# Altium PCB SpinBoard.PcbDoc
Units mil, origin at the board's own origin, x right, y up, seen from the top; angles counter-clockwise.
Board outline 4528 x 1083 mil, 2 copper layers (Top Layer, Bottom Layer), stack 26.422 mil thick; 101 components, 94 nets, 297 pads, 156 vias.
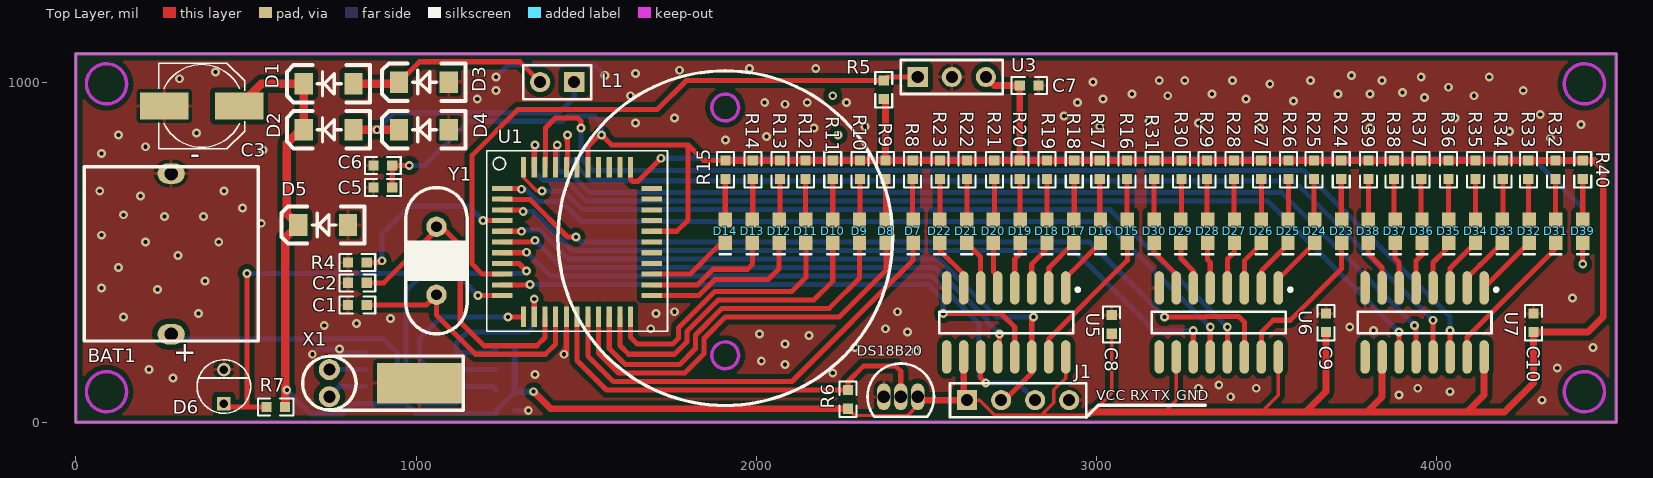
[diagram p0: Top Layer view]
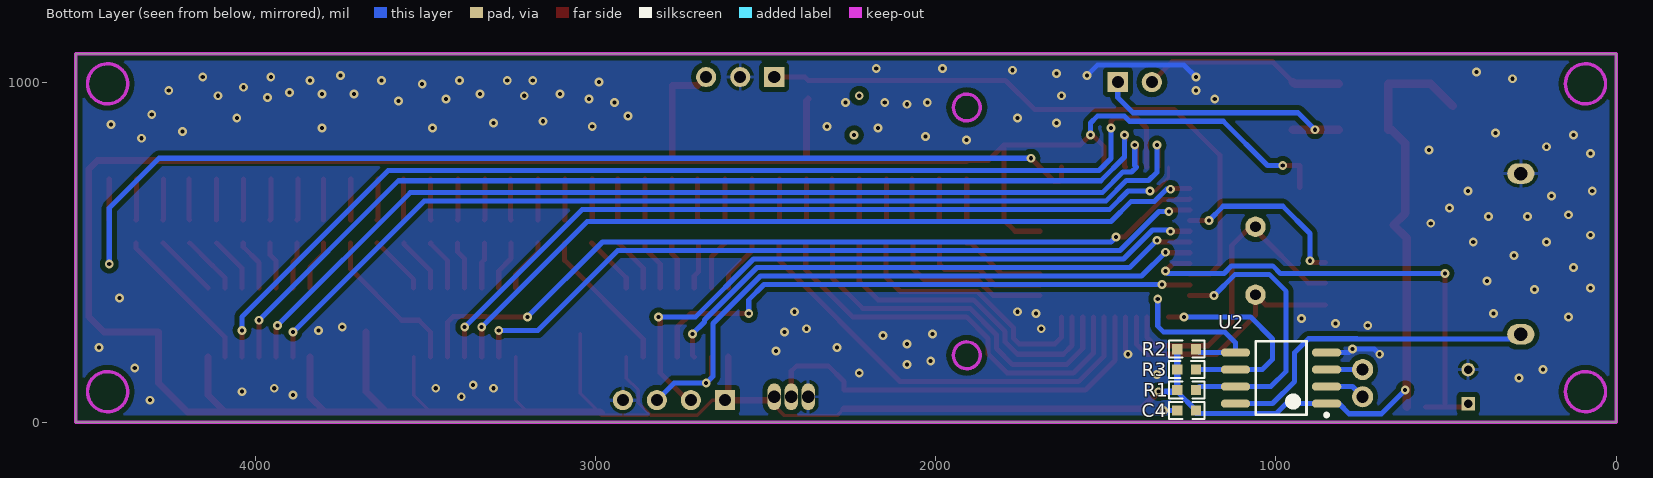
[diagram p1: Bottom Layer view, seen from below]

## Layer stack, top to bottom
Top Solder: solder mask 0.4, Solder Resist, Dk 3.5
Top Layer: signal copper 1.4
Dielectric 1: dielectric 23.622, FR-4, Dk 4.8
Bottom Layer: signal copper 1.4
Bottom Solder: solder mask 0.4, Solder Resist, Dk 3.5

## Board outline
0,0 4528,0 4528,1083 0,1083

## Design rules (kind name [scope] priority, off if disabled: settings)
Clearance Clearance_Poly [InPolygon] p1: gap=15 ignorepadtopadclearanceinfootprint=FALSE
Clearance [All] p2: gap=10 ignorepadtopadclearanceinfootprint=FALSE
MinimumSolderMaskSliver [All] p1: minsoldermaskwidth=1
PolygonConnect PolygonConnect_Via [IsVia] p1: connectstyle=Direct reliefconductorwidth=10 reliefentries=4 polygonreliefangle="90 Angle" airgapwidth=10
PolygonConnect [All] p2: connectstyle=Relief reliefconductorwidth=10 reliefentries=4 polygonreliefangle="90 Angle" airgapwidth=10
RoutingVias [All] p1: holewidth=12 width=26 viastyle="Through Hole" minholewidth=12 minwidth=20 maxholewidth=28 maxwidth=50
SilkToSilkClearance [All] p1 off: silktosilkclearance=10
SilkToSolderMaskClearance [IsPad] p1 off: minsilkscreentomaskgap=10 clearancetoexposedcopper=TRUE
SolderMaskExpansion [All] p1: expansion=4
Width [All] p1: maxlimit=50 minlimit=10 preferedwidth=15
27 further rules are at their usual default settings.

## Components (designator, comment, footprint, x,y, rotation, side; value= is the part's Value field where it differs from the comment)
BAT1 "3V" CR1220-2 280,495 r180 top
C1 "20p" 0603 855,345 r180 top
C2 "20p" 0603 855,410 r180 top
C3 "Cap Pol1" C-RB-SD6 370,930 r180 top value=470uF
C4 "0.1uF" 0603 1235,35 r0 bottom
C5 "0.1uF" 0603 875,690 r0 top
C6 "10uF" 0603 875,755 r0 top
C7 "4.7uF" 0603 2830,990 r180 top
C8 "0.1uF" 0603 3045,315 r270 top
C9 "0.1uF" 0603 3675,320 r270 top
C10 "0.1uF" 0603 4285,320 r270 top
D1 "Diode" LL34 670,995 r180 top
D2 "Diode" LL34 670,860 r180 top
D3 "Diode" LL34 950,1000 r180 top
D4 "Diode" LL34 950,860 r180 top
D5 "5.1V" LL34 654,580 r180 top
D6 "Photo Sen" LED-3mm 435,105 r90 top
D7 "IR Receiver" CD1608-0603 2461.18,561.02 r270 top
D8 "IR Receiver" CD1608-0603 2382.44,561.02 r270 top
D9 "IR Receiver" CD1608-0603 2303.7,561.02 r270 top
D10 "IR Receiver" CD1608-0603 2224.96,561.02 r270 top
D11 "IR Receiver" CD1608-0603 2146.22,561.02 r270 top
D12 "IR Receiver" CD1608-0603 2067.48,561.02 r270 top
D13 "IR Receiver" CD1608-0603 1988.74,561.02 r270 top
D14 "IR Receiver" CD1608-0603 1909.02,561.02 r270 top
D15 "IR Receiver" CD1608-0603 3091.1,561.02 r270 top
D16 "IR Receiver" CD1608-0603 3012.36,561.02 r270 top
D17 "IR Receiver" CD1608-0603 2933.62,561.02 r270 top
D18 "IR Receiver" CD1608-0603 2854.88,561.02 r270 top
D19 "IR Receiver" CD1608-0603 2776.14,561.02 r270 top
D20 "IR Receiver" CD1608-0603 2697.4,561.02 r270 top
D21 "IR Receiver" CD1608-0603 2618.66,561.02 r270 top
D22 "IR Receiver" CD1608-0603 2539.92,561.02 r270 top
D23 "IR Receiver" CD1608-0603 3721.02,561.02 r270 top
D24 "IR Receiver" CD1608-0603 3642.28,561.02 r270 top
D25 "IR Receiver" CD1608-0603 3563.54,561.02 r270 top
D26 "IR Receiver" CD1608-0603 3484.8,561.02 r270 top
D27 "IR Receiver" CD1608-0603 3406.06,561.02 r270 top
D28 "IR Receiver" CD1608-0603 3327.32,561.02 r270 top
D29 "IR Receiver" CD1608-0603 3248.58,561.02 r270 top
D30 "IR Receiver" CD1608-0603 3169.84,561.02 r270 top
D31 "IR Receiver" CD1608-0603 4350.94,561.02 r270 top
D32 "IR Receiver" CD1608-0603 4272.2,561.02 r270 top
D33 "IR Receiver" CD1608-0603 4193.46,561.02 r270 top
D34 "IR Receiver" CD1608-0603 4114.72,561.02 r270 top
D35 "IR Receiver" CD1608-0603 4035.98,561.02 r270 top
D36 "IR Receiver" CD1608-0603 3957.24,561.02 r270 top
D37 "IR Receiver" CD1608-0603 3878.5,561.02 r270 top
D38 "IR Receiver" CD1608-0603 3799.76,561.02 r270 top
D39 "IR Receiver" CD1608-0603 4429.69,561.02 r270 top
DS18B20 "DS18B20" TO-92A 2425,75 r270 top (schematic designator U4)
J1 "UART" HDR1X4 2620,65 r0 top
L1 "次级线圈" HDR1X2 1465,1000 r180 top value=10mH
R1 "10k" 0603 1235,95 r0 bottom
R2 "10k" 0603 1235,215 r0 bottom
R3 "10k" 0603 1290,155 r180 bottom
R4 "1k" 0603 800,470 r0 top
R5 "10k" 0603 2375,1005 r270 top
R6 "10k" 0603 2270,40 r90 top
R7 "10k" 0603 560,45 r0 top
R8 "560" 0603 2460,715 r90 top
R9 "560" 0603 2380,715 r90 top
R10 "560" 0603 2305,715 r90 top
R11 "560" 0603 2225,715 r90 top
R12 "560" 0603 2145,715 r90 top
R13 "560" 0603 2070,715 r90 top
R14 "560" 0603 1990,715 r90 top
R15 "560" 0603 1910,715 r90 top
R16 "560" 0603 3090,715 r90 top
R17 "560" 0603 3010,715 r90 top
R18 "560" 0603 2935,715 r90 top
R19 "560" 0603 2855,715 r90 top
R20 "560" 0603 2775,715 r90 top
R21 "560" 0603 2700,715 r90 top
R22 "560" 0603 2620,715 r90 top
R23 "560" 0603 2540,715 r90 top
R24 "560" 0603 3720,715 r90 top
R25 "560" 0603 3640,715 r90 top
R26 "560" 0603 3565,715 r90 top
R27 "560" 0603 3485,715 r90 top
R28 "560" 0603 3405,715 r90 top
R29 "560" 0603 3325,715 r90 top
R30 "560" 0603 3250,715 r90 top
R31 "560" 0603 3170,715 r90 top
R32 "560" 0603 4350,715 r90 top
R33 "560" 0603 4270,715 r90 top
R34 "560" 0603 4195,715 r90 top
R35 "560" 0603 4115,715 r90 top
R36 "560" 0603 4035,715 r90 top
R37 "560" 0603 3955,715 r90 top
R38 "560" 0603 3875,715 r90 top
R39 "560" 0603 3800,715 r90 top
R40 "560" 0603 4430,715 r90 top
U1 "STC12C5A60S2" TQFP-44 1253.51,687.51 r0 top
U2 "DS1302S" SOIC8WA_N 985,130 r0 bottom
U3 "irDA" HDR1X3 2475,1015 r0 top
U5 "74HC595" SOIC-16 2735,293.54 r270 top
U6 "74HC595" SOIC-16 3360,293.54 r270 top
U7 "74HC595" SOIC-16 3965,293.54 r270 top
X1 "32.768K" XTAL-32k 745,115 r0 top
Y1 "XTAL" X-HC-49S 1060,475 r270 top value=18.432M

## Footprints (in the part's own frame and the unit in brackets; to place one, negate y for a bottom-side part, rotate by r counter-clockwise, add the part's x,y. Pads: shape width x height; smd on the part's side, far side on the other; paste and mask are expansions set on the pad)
0603 [mil] "贴片0603"
  rect 30x30 smd: 1(0,0) 2(55,0)
  silkscreen extent -25,-25 80,25
C-RB-SD6 [mm] "贴片铝电解"
  rect 3.6x2 smd: 1(-2.794,0) 2(2.794,0)
  silkscreen extent -3.2,-3.2 3.2,3.2
CD1608-0603 [mm] "Chip Diode; Body 1.6 x 0.8 mm (LxW typ)"
  rect 1.1x1 smd: 1(-0.85,0) 2(0.85,0)
  silkscreen extent 1.7,-0.4 1.7,0.4
CR1220-2 [mil] "CR1220 DIP"
  oval 80x60 hole 39.37: 1(0,236.22) 2(0,-236.22)
  silkscreen extent -256,-256 256,256
HDR1X2 [mm] "Connector; Header; 2 Position"
  rect 1.5x1.5 hole 0.9: 1(0,0)
  round 1.5 hole 0.9: 2(2.54,0)
  silkscreen extent -1.27,-1.27 3.81,1.27
HDR1X3 [mm] "Connector; Header; 3 Position"
  rect 1.5x1.5 hole 0.9: 1(0,0)
  round 1.5 hole 0.9: 2(2.54,0) 3(5.08,0)
  silkscreen extent -1.27,-1.27 6.35,1.27
HDR1X4 [mm] "Connector; Header; 4 Position"
  rect 1.5x1.5 hole 0.9: 1(0,0)
  round 1.5 hole 0.9: 2(2.54,0) 3(5.08,0) 4(7.62,0)
  silkscreen extent -1.27,-1.27 8.89,1.27
LED-3mm [mil] "Typical INFRARED GaAs LED; 2 Leads"
  rect 40x40 hole 25: 1(-50,0)
  round 40 hole 25: 2(50,0)
  silkscreen extent -79,-79 79,79
LL34 [mil]
  rect 54x64 smd: 1(-146,0) 2(0,0)
  silkscreen extent -195,-55 50,55
SOIC8WA_N [mm] "SOP, 8-Leads, Body 5.3x5.3mm, Pitch 1.27mm, IPC Medium Density"
  oval 2.2x0.6 smd: 1(-3.4,1.905) 2(-3.4,0.635) 3(-3.4,-0.635) 4(-3.4,-1.905) 5(3.4,-1.905) 6(3.4,-0.635) 7(3.4,0.635) 8(3.4,1.905)
  silkscreen extent -3.52,-2.75 1.9,2.88, body extent -2.73,-2.75 2.73,2.75, height 2.13
SOIC-16 [mm]
  oval 2.5x0.7 smd: 1(-2.577,4.445) 2(-2.577,3.175) 3(-2.577,1.905) 4(-2.577,0.635) 5(-2.577,-0.635) 6(-2.577,-1.905) 7(-2.577,-3.175) 8(-2.577,-4.445) 9(2.577,-4.445) 10(2.577,-3.175) 11(2.577,-1.905) 12(2.577,-0.635) 13(2.577,0.635) 14(2.577,1.905) 15(2.577,3.175) 16(2.577,4.445)
  silkscreen extent -2.57,-5 0.8,5.47, body extent -2.88,-4.92 2.92,4.88, height 1.75
TO-92A [mm]
  oval 2x1 hole 0.9: 1(0,-1.27) 2(0,0) 3(0,1.27)
  silkscreen extent -2.48,-2.48 1.5,2.48
TQFP-44 [mil]
  rect 60x15 smd: 1(-0.01,-0.03) 2(-0.01,-31.53) 3(-0.01,-63.02) 4(-0.01,-94.52) 5(-0.01,-126.02) 6(-0.01,-157.51) 7(-0.01,-189.01) 8(-0.01,-220.5) 9(-0.01,-252) 10(-0.01,-283.5) 11(-0.01,-314.99) 23(439.99,-314.99) 24(439.99,-283.5) 25(439.99,-252) 26(439.99,-220.5) 27(439.99,-189.01) 28(439.99,-157.51) 29(439.99,-126.02) 30(439.99,-94.52) 31(439.99,-63.02) 32(439.99,-31.53) 33(439.99,-0.03)
  rect 15x60 smd: 12(62.51,-377.51) 13(94.01,-377.51) 14(125.5,-377.51) 15(157,-377.51) 16(188.5,-377.51) 17(219.99,-377.51) 18(251.49,-377.51) 19(282.98,-377.51) 20(314.48,-377.51) 21(345.98,-377.51) 22(377.47,-377.51) 34(377.47,62.49) 35(345.98,62.49) 36(314.48,62.49) 37(282.98,62.49) 38(251.49,62.49) 39(219.99,62.49) 40(188.5,62.49) 41(157,62.49) 42(125.5,62.49) 43(94.01,62.49) 44(62.51,62.49)
  silkscreen extent -46,-420 486,111
X-HC-49S [mil] "插件晶振"
  round 60 hole 32: 1(-100,0) 2(100,0)
  silkscreen extent -215,-90 215,90
XTAL-32k [mil]
  round 62 hole 35.43: 1(0,40) 2(0,-40)
  rect 250x120 smd: 3(265,0)
  silkscreen extent -79,-80 394,80

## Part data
BAT1: library part BATTERY
C1 C2 C4 C5 C6 C7 C8 C9 C10: library part Cap, "Capacitor"
C3: "Polarized Capacitor (Radial)"
D1 D2 D3 D4: "Default Diode"
D5: library part "D Zener", "Zener Diode"
D6: "Photosensitive Diode"
D7 D8 D9 D10 D11 D12 D13 D14 D15 D16 D17 D18 D19 D20 D21 D22 D23 D24 D25 D26 D27 D28 D29 D30 D31 D32 D33 D34 D35 D36 D37 D38 D39: library part LED0, "Typical INFRARED GaAs LED"
DS18B20: "温度传感器"
J1: library part "Header 4", "Header, 4-Pin"
L1: library part Inductor, "Inductor"
R1 R2 R3 R4 R5 R6 R7 R8 R9 R10 R11 R12 R13 R14 R15 R16 R17 R18 R19 R20 R21 R22 R23 R24 R25 R26 R27 R28 R29 R30 R31 R32 R33 R34 R35 R36 R37 R38 R39 R40: library part Res1, "Resistor"
U2: "Trickle Charge Timekeeping Chip"
U3: library part "Header 3", "Header, 3-Pin"
U5 U6 U7: "移位寄存器"
X1: library part CRYSTAL
Y1: "晶振"

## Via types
v1: diameter 26, hole 12, Top Layer to Bottom Layer, tented both sides, 156 vias

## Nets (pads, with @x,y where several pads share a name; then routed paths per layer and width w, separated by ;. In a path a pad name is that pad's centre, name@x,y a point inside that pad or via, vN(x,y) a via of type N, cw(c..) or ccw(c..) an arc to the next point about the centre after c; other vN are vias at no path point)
GND: BAT1.2 C1.2 C2.2 C3.2 C4.2 C5.1 C6.1 C7.1 C8.1 C9.1 C10.1 D3.1 D4.1 D5.1 D6.2 DS18B20.1 J1.4 R4.1 U1.16 U2.4 U3.2 U5.8 U6.8 U7.8 X1.3 | length 661.3
  Top Layer w15: v1(1435,200) 1442.01,207.01 U1.16
  Bottom Layer w15: v1(695,200) 710,215 v1(775,215) 785,205 U2.4 ; v1(1235,1015) 1270,1050 1525,1050 v1(1555,1020) ; C4.2 v1@1325,35
  other v1: 1330,35 4310,65 3395,75 3890,80 4040,90 3300,100 3470,100 3945,100 3360,110 285,130 1350,140 2225,145 215,155 4355,160 2085,170 2015,180 2470,210 2290,220 4460,220 2085,230 2155,255 2010,260 2445,265 3815,270 1690,275 2380,275 3745,280 730,285 825,290 925,305 140,310 360,320 1705,320 1760,325 2415,325 4400,365 240,390 75,395 380,415 125,455 300,490 205,530 420,530 75,550 545,585 260,605 375,605 140,610 490,630 190,665 70,680 435,680 75,790 550,800 205,810 1910,830 4335,835 2030,840 125,845 355,850 4215,855 2170,865 3480,865 3805,865 2320,870 3010,870 4425,875 1645,880 3300,880 3155,885 1760,895 4055,895 2905,900 4305,905 2085,935 2025,940 2150,940 2265,940 2945,940 3580,945 1180,950 3020,950 3440,950 3965,955 1630,960 3210,960 4110,960 3105,965 3340,965 3710,965 3805,965 3900,970 1235,975 4255,975 4035,985 3510,995 2990,1000 3185,1005 3260,1005 3400,1005 3630,1005 3840,1005 305,1010 3955,1015 4155,1015 3750,1020 1645,1025 410,1030 1775,1035 1980,1040 2175,1040
IO: R3.2 U1.12 U2.6 | length 630.4
  Top Layer w15: v1(1270,310) U1.12
  Bottom Layer w15: R3.2 U2.6 1040,155 1010,185 1010,245 1075,310 v1(1270,310)
IR: R5.1 U1.9 U3.1 | length 1826
  Top Layer w15: U1.9 1194.49,435.51 1165,465 1165,785 1300,920 1710,920 1795,1005 R5.1 2385,1015 U3.1
NetBAT1_1: BAT1.1 U2.8 | length 973.5
  Bottom Layer w15: BAT1.1 293.78,245 761.87,245 762.37,245.5 904.5,245.5 945,205 945,120 1010,55 U2.8
NetC1_1: C1.1 U1.15 Y1.2 | length 767.7
  Top Layer w15: C1.1 1030,345 Y1.2 1060,315 1175,200 1380,200 1410.51,230.51 U1.15
NetC2_1: C2.1 U1.14 Y1.1 | length 945.9
  Top Layer w15: C2.1 905,410 1060,565 Y1.1 1075,575 1130,520 1130,295 1200,225 1355,225 1379.02,249.02 U1.14
NetD1_1: D1.1 D3.2 L1.2 | length 600.8
  Top Layer w15: D3.2 1010,1060 1305,1060 L1.2
  Top Layer w25: D1.1 945,995 D3.2
NetD2_1: D2.1 D4.2 L1.1 | length 798.4
  Top Layer w25: D2.1 v1(885,860) D4.2
  Bottom Layer w15: v1(885,860) 935,910 1420,910 1465,955 L1.1
NetD7_1: D7.1 R8.1 | length 121
  Top Layer w15: R8.1 2460,595.67 D7.1
NetD8_1: D8.1 R9.1 | length 121.5
  Top Layer w15: R9.1 2380,596.93 D8.1
NetD9_1: D9.1 R10.1 | length 121.1
  Top Layer w15: D9.1 2305,595.79 R10.1
NetD10_1: D10.1 R11.1 | length 120.5
  Top Layer w15: D10.1 D10.1 R11.1
NetD11_1: D11.1 R12.1 | length 121
  Top Layer w15: R12.1 2145,595.71 D11.1
NetD12_1: D12.1 R13.1 | length 121.6
  Top Layer w15: D12.1 2070,597.01 R13.1
NetD13_1: D13.1 R14.1 | length 121
  Top Layer w15: D13.1 1990,595.75 R14.1
NetD14_1: D14.1 R15.1 | length 120.9
  Top Layer w15: D14.1 1909.02,714.02 R15.1
NetD15_1: D15.1 R16.1 | length 121
  Top Layer w15: R16.1 3090,595.59 D15.1
NetD16_1: D16.1 R17.1 | length 121.5
  Top Layer w15: R17.1 3010,596.85 D16.1
NetD17_1: D17.1 R18.1 | length 121.1
  Top Layer w15: D17.1 2935,595.87 R18.1
NetD18_1: D18.1 R19.1 | length 120.6
  Top Layer w15: D18.1 2855,594.61 R19.1
NetD19_1: D19.1 R20.1 | length 121
  Top Layer w15: R20.1 2775,595.63 D19.1
NetD20_1: D20.1 R21.1 | length 121.6
  Top Layer w15: D20.1 2700,597.09 R21.1
NetD21_1: D21.1 R22.1 | length 121.1
  Top Layer w15: D21.1 2620,595.83 R22.1
NetD22_1: D22.1 R23.1 | length 120.5
  Top Layer w15: D22.1 2540,594.57 R23.1
NetD23_1: D23.1 R24.1 | length 120.9
  Top Layer w15: R24.1 3720,595.51 D23.1
NetD24_1: D24.1 R25.1 | length 121.5
  Top Layer w15: R25.1 3640,596.77 D24.1
NetD25_1: D25.1 R26.1 | length 121.1
  Top Layer w15: D25.1 3565,595.94 R26.1
NetD26_1: D26.1 R27.1 | length 120.6
  Top Layer w15: D26.1 3485,594.68 R27.1
NetD27_1: D27.1 R28.1 | length 121
  Top Layer w15: R28.1 3405,595.55 D27.1
NetD28_1: D28.1 R29.1 | length 121.5
  Top Layer w15: R29.1 3325,596.81 D28.1
NetD29_1: D29.1 R30.1 | length 121.1
  Top Layer w15: D29.1 3250,595.91 R30.1
NetD30_1: D30.1 R31.1 | length 120.6
  Top Layer w15: D30.1 3170,594.65 R31.1
NetD31_1: D31.1 R32.1 | length 120.9
  Top Layer w15: R32.1 4350,595.43 D31.1
NetD32_1: D32.1 R33.1 | length 121.4
  Top Layer w15: R33.1 4270,596.69 D32.1
NetD33_1: D33.1 R34.1 | length 121.1
  Top Layer w15: D33.1 4195,596.02 R34.1
NetD34_1: D34.1 R35.1 | length 120.6
  Top Layer w15: D34.1 4115,594.76 R35.1
NetD35_1: D35.1 R36.1 | length 120.9
  Top Layer w15: R36.1 4035,595.47 D35.1
NetD36_1: D36.1 R37.1 | length 121.4
  Top Layer w15: R37.1 3955,596.73 D36.1
NetD37_1: D37.1 R38.1 | length 122
  Top Layer w15: R38.1 3875,597.99 D37.1
NetD38_1: D38.1 R39.1 | length 120.6
  Top Layer w15: D38.1 3800,594.72 R39.1
NetD39_1: D39.1 R40.1 | length 120.6
  Top Layer w15: D39.1 4430,594.8 R40.1
NetR4_2: R4.2 U1.4 | length 531.1
  Top Layer w15: R4.2 895,470 v1(900,475) ; v1(1197.01,592.99) U1.4
  Bottom Layer w15: v1(900,475) 900,555 980,635 1155,635 v1(1197.01,592.99)
NetU2_2: U2.2 X1.2 | length 118.6
  Bottom Layer w15: X1.2 775,105 U2.2
NetU2_3: U2.3 X1.1 | length 106.1
  Bottom Layer w15: X1.1 U2.3
nRST: R2.1 U1.13 U2.5 | length 530.4
  Top Layer w15: U1.13 v1(1347.52,362.48)
  Bottom Layer w15: R2.1 1225,205 U2.5 1118.86,233.86 1150,265 1330,265 1347.52,282.52 v1(1347.52,362.48)
OEA: U1.10 U5.13 | length 1670
  Top Layer w15: U1.10 1334.01,404.02 v1(1335,405) ; v1(2550,320) 2720,320 2760,280 U5.13
  Bottom Layer w15: v1(1335,405) 2505,405 2550,360 v1(2550,320)
OEB: U1.44 U6.13 | length 2369.7
  Top Layer w10: U1.44 1316.02,718.98 1355,680 v1(1370,680)
  Top Layer w15: U6.13 v1(3385,280)
  Bottom Layer w15: v1(1370,680) 1435,680 1490,625 3040,625 v1(3385,280)
OEC: U1.40 U7.13 | length 3016.3
  Top Layer w15: U1.40 1445.5,753.49 1445.5,827.63 1442.01,831.13 1442.01,842.01 v1(1445,845) ; U7.13 v1(3990,300)
  Bottom Layer w15: v1(1445,845) 1445.5,844.5 1445.5,802.37 1445,801.87 1445,780 1515,710 3580,710 v1(3990,300)
P32: D6.1 R7.1 U1.8 | length 1446.5
  Top Layer w15: D6.1 445,45 502.5,45 ; v1(502.5,437.5) 502.5,45 ; R7.1 502.5,45 ; U1.8 1302.99,467.01 v1(1325,445)
  Bottom Layer w15: v1(502.5,437.5) 987.14,437.5 1009.64,460 1130.36,460 1152.86,437.5 1317.5,437.5 v1(1325,445)
R1: D7.2 U1.18 | length 1301.2
  Top Layer w15: U1.18 1505,195 1580,120 2105,120 2461.18,476.18 D7.2
R2: D8.2 U1.19 | length 1208.4
  Top Layer w15: U1.19 1536.5,203.5 1595,145 1790,145 1846.6,201.6 1846.6,246.6 1910,310 2245,310 2382.44,447.44 D8.2
R3: D9.2 U1.20 | length 1080.8
  Top Layer w15: U1.20 1567.99,217.01 1615,170 1775,170 1821.6,216.6 1821.6,256.95 1899.64,335 2215,335 2303.7,423.7 D9.2
R4: D10.2 U1.21 | length 940.2
  Top Layer w15: U1.21 1599.49,225.51 1625,200 1760,200 1796.6,236.6 1796.6,267.31 1889.29,360 2170,360 2224.96,414.96 D10.2
R5: D11.2 U1.22 | length 784.7
  Top Layer w15: U1.22 1630.98,249.02 1650,230 1754.64,230 1771.6,246.95 1771.6,277.66 1878.93,385 2105,385 2146.22,426.22 D11.2
R6: D12.2 U1.23 | length 482.2
  Top Layer w15: U1.23 1831.1,372.52 1878.58,420 2035,420 2067.48,452.48 D12.2
R7: D13.2 U1.24 | length 383.8
  Top Layer w15: U1.24 1827.24,404.02 1873.22,450 1975,450 1988.74,463.74 D13.2
R8: D14.2 U1.25 | length 253.6
  Top Layer w15: U1.25 1805.51,435.51 1897.56,527.56 D14.2
R9: D15.2 U5.15 | length 431.2
  Top Layer w15: U5.15 2860,245 3091.1,476.1 D15.2
R10: D16.2 U5.1 | length 175
  Top Layer w15: U5.1 2910,425.2 D16.2
R11: D17.2 U5.2 | length 163.1
  Top Layer w15: U5.2 2860,453.94 D17.2
R12: D18.2 U5.3 | length 151.1
  Top Layer w15: U5.3 2810,465 2854.88,509.88 D18.2
R13: D19.2 U5.4 | length 139.2
  Top Layer w15: U5.4 2760,480 2776.14,496.14 D19.2
R14: D20.2 U5.5 | length 137.8
  Top Layer w15: D20.2 2697.4,442.6 2710,430 U5.5
R15: D21.2 U5.6 | length 149.7
  Top Layer w15: D21.2 2660,486.22 U5.6
R16: D22.2 U5.7 | length 161.6
  Top Layer w15: D22.2 2539.92,505.08 2610,435 U5.7
R17: D23.2 U6.15 | length 462.5
  Top Layer w15: U6.15 3485,265 3520,300 3570,300 3721.02,451.02 D23.2
R18: D24.2 U6.1 | length 177
  Top Layer w15: U6.1 3535,420.28 D24.2
R19: D25.2 U6.2 | length 165.1
  Top Layer w15: U6.2 3485,445 3563.54,523.54 D25.2
R20: D26.2 U6.3 | length 153.2
  Top Layer w15: U6.3 3435,475 3484.8,524.8 D26.2
R21: D27.2 U6.4 | length 141.3
  Top Layer w15: U6.4 3385,480 3406.06,501.06 D27.2
R22: D28.2 U6.5 | length 135.7
  Top Layer w15: D28.2 3327.32,477.68 3335,470 U6.5
R23: D29.2 U6.6 | length 147.6
  Top Layer w15: D29.2 3248.58,481.42 3285,445 U6.6
R24: D30.2 U6.7 | length 159.5
  Top Layer w15: D30.2 3169.84,500.16 3235,435 U6.7
R25: D31.2 U7.15 | length 443.6
  Top Layer w15: U7.15 4090,250 4350.94,510.94 D31.2
R26: D32.2 U7.1 | length 187.3
  Top Layer w15: U7.1 4140,395.35 D32.2
R27: D33.2 U7.2 | length 175.8
  Top Layer w15: U7.2 4090,424.67 4127.04,461.71 4127.62,461.71 D33.2
R28: D34.2 U7.3 | length 163.5
  Top Layer w15: U7.3 4040,452.83 D34.2
R29: D35.2 U7.4 | length 151.6
  Top Layer w15: U7.4 3990,470 4035.98,515.98 D35.2
R30: D36.2 U7.5 | length 139.7
  Top Layer w15: U7.5 3940,475 3957.24,492.24 D36.2
R31: D37.2 U7.6 | length 137.3
  Top Layer w15: D37.2 3878.5,481.5 3890,470 U7.6
R32: D38.2 U7.7 | length 149.2
  Top Layer w15: D38.2 3799.76,495.24 3840,455 U7.7
R33: D39.2 U1.34 | length 3153.9
  Top Layer w15: U1.34 1630.98,714.02 1636.89,708.11 1651.89,708.11 v1(1720,776.22) ; D39.2 4429.69,465.32 v1(4430,465)
  Bottom Layer w15: v1(1720,776.22) 4283.78,776.22 4430,630 v1(4430,465)
RCLA: U1.6 U5.12 | length 1650.8
  Top Layer w15: U1.6 1254,530.5 1345.5,530.5 v1(1350,535) ; U5.12 2715,197.09 v1(2715,260)
  Bottom Layer w15: v1(1350,535) 1430,455 2525.71,455 2680,300.71 2680,295 v1(2715,260)
RCLB: U1.1 U6.12 | length 2338.2
  Top Layer w15: U1.1 1307.52,687.48 v1(1310,685) ; U6.12 v1(3335,280)
  Bottom Layer w15: v1(1310,685) 1321.87,685 1357.37,649.5 1425.5,649.5 1485,590 3025,590 v1(3335,280)
RCLC: U1.41 U7.12 | length 2948.9
  Top Layer w15: U1.41 1410.51,814.49 1411.02,815 v1(1415,815) ; v1(3935,285) 3940,280 U7.12
  Bottom Layer w15: v1(1415,815) 1415,755 1410,750 1424.5,735.5 1450.21,735.5 1510.71,675 3545,675 v1(3935,285)
RXD: J1.2 U1.5 U5.14 | length 1959.2
  Top Layer w15: U1.5 v1(1310,561.5) ; J1.2 2730,65 2810,145 U5.14 2810,305 v1(2815,310)
  Bottom Layer w15: v1(1310,561.5) 1314,565.5 1362.63,565.5 1448.13,480 2536.07,480 2706.07,310 v1(2815,310)
SCLB: U1.3 U6.11 | length 2256.2
  Top Layer w15: U1.3 1310.51,624.49 v1(1315,620) ; U6.11 v1(3285,270)
  Bottom Layer w15: v1(1315,620) 1343.49,620 1458.49,505 2935,505 3170,270 v1(3285,270)
SCLC: U1.43 U7.11 | length 2953.6
  Top Layer w15: U1.43 1347.52,812.52 v1(1350,815) ; U7.11 v1(3890,265)
  Bottom Layer w15: v1(1350,815) 1350,735 1374.5,710.5 1439.86,710.5 1500.36,650 3505,650 v1(3890,265)
SCLK: R1.1 U1.11 U2.7 | length 852.9
  Top Layer w15: v1(1182.48,372.52) U1.11
  Bottom Layer w15: v1(1182.48,372.52) 1120,435 1020,435 970,385 970,150 1015,105 U2.7 1225,105 R1.1
SDIB: U1.2 U6.14 | length 2434.3
  Top Layer w15: U1.2 1254.99,654.5 1335.5,654.5 1445,545 v1(1470,545) ; v1(3200,310) 3321.87,310 3322.37,310.5 3419.5,310.5 3435,295 U6.14
  Bottom Layer w15: v1(1470,545) 1485,530 2980,530 v1(3200,310)
SDIC: U1.42 U7.14 | length 3212.3
  Top Layer w15: U1.42 1380.5,751.48 1380.5,865.5 1410,895 1475,895 1485,885 v1(1485,865) ; U7.14 v1(4040,270)
  Bottom Layer w15: v1(1485,865) 1485,775.36 1520.36,740 3610,740 4040,310 v1(4040,270)
TMP: DS18B20.2 R6.2 U1.17 | length 1240.7
  Top Layer w15: U1.17 1473.5,181.5 1560,95 R6.2 2270,120 2315,165 2410,165 2425,150 DS18B20.2
TXD: J1.3 U1.7 U5.11 | length 1921.6
  Top Layer w15: U1.7 1323.5,498.5 v1(1325,500) ; U5.11 2660,130 v1(2675,115)
  Bottom Layer w15: v1(1325,500) 1395,430 2515.36,430 2655,290.36 2655,135 v1(2675,115) 2770,115 J1.3
VCC: C3.1 C4.1 C5.2 C6.2 C7.2 C8.2 C9.2 C10.2 D1.2 D2.2 D5.2 DS18B20.3 J1.1 R1.2 R2.2 R3.1 R5.2 R6.1 R7.2 R8.2 R9.2 R10.2 R11.2 R12.2 R13.2 R14.2 R15.2 R16.2 R17.2 R18.2 R19.2 R20.2 R21.2 R22.2 R23.2 R24.2 R25.2 R26.2 R27.2 R28.2 R29.2 R30.2 R31.2 R32.2 R33.2 R34.2 R35.2 R36.2 R37.2 R38.2 R39.2 R40.2 U1.29 U1.38 U2.1 U3.3 U5.10 U5.16 U6.10 U6.16 U7.10 U7.16 | length 12338.8
  Top Layer w10: R6.1 2290,20 2445,20 2475,50 DS18B20.3 ; J1.1 2657.03,65 2701.56,20.47 2838.44,20.47 2842.97,25 ; U5.16 2910,130 2875,95 2875,57.03 2842.97,25 ; 2980.47,20.47 2847.5,20.47 2842.97,25 ; 2990,30 3045,85 C8.2 ; 3200,30 3235,65 U6.10 ; 3485,30 3535,80 U6.16
  Top Layer w15: C5.2 C6.2 v1(980,755) ; U1.38 1505,810 1540,845 v1(1545,845) 1575,815 1800,815 ; U1.29 1766.5,561.5 1800,595 1800,815 ; R15.2 1845,770 1800,815
  Top Layer w20: v1(1345,90) 1395,40 R6.1 ; R15.2 R14.2 R13.2 R12.2 R11.2 R10.2 R9.2 ; R5.2 2380,945 R9.2 ; DS18B20.3 2485,65 J1.1 2610,75 U5.10 ; U3.3 2700,990 C7.2 R20.2 ; 2980.47,25 2985.47,30 2990,30 3200,30 3485,30 3615,30 ; C9.2 3675,90 3615,30 ; U7.10 3840,75 3795,30 ; U7.16 4140,80 4090,30 ; R9.2 R8.2 R23.2 R22.2 R21.2 R20.2 ; R20.2 R19.2 R18.2 R17.2 R16.2 R31.2 R30.2 R29.2 R28.2 R27.2 R26.2 R25.2 R24.2 R39.2 R38.2 R37.2 R36.2 R35.2 R34.2 R33.2 R32.2 R40.2 4465,770 4490,745 4490,310 4445,265 C10.2 4285,115 4200,30 4090,30 ; 3615,30 3795,30 ; 3795,30 4090,30
  Top Layer w25: C3.1 545,995 D1.2 D2.2 660,860 620,820 620,614 D5.2 615,541 R7.2
  Bottom Layer w15: v1(620,95) 690,25 785,25 815,55 U2.1 970,55 999.31,25.69 1235,25.69 C4.1 1290,90 R1.2 ; v1(980,755) 1025,755 1155,885 1430.36,885 1445.36,900 1525,900 1545,880 v1(1545,845)
  Bottom Layer w20: R2.2 R3.1 R1.2 1295,90 v1(1345,90)
pads on no net: U1.26 U1.27 U1.28 U1.30 U1.31 U1.32 U1.33 U1.35 U1.36 U1.37 U1.39 U5.9 U6.9 U7.9
copper on no net:
  other v1: 2240,845 2225,960

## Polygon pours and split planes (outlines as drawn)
GND on Top Layer "GND_L01_P000" (solid, remove dead copper, pour order 0): 0,1083 0,0 4528,0 4528,1083
GND on Bottom Layer "GND_L02_P002" (solid, remove dead copper, pour order 2): 0,1083 0,0 4528,0 4528,1083

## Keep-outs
Keep-Out Layer:
  circle w10: c1909,196.85 r39.37
  circle w10: c1909,925.51 r39.37
  circle w10: c4435,90 r59.06
  circle w10: c4435,995 r59.06
  circle w10: c90,90 r59.06
  circle w10: c90,995 r59.06
  lines w10: 0,0 0,1083 4528,1083 4528,0 0,0

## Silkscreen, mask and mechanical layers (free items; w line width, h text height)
Top Overlay:
  circle w10: c1909.02,541.34 r492.13
  lines w10: 2970,15 3005,50 3320,50
  text "VCC" at 3000,65 h30
  text "RX" at 3100,65 h30
  text "TX" at 3165,65 h30
  text "GND" at 3235,65 h30
Drill Drawing:
  lines w15: 4774.12,170 9380.89,170 ; 4774.12,920 9380.89,920 ; 5325,20 5325,1070 ; 5914.84,20 5914.84,1070 ; 7014.52,20 7014.52,1070 ; 7520.4,20 7520.4,1070 ; 8254.2,20 8254.2,1070 ; 4774.12,20 9380.89,20 9380.89,1070 4774.12,1070 4774.12,20
  text "Symbol" at 4864.12,965 h72
  text "Count" at 5370,965 h72
  text "Hole Size" at 5959.84,965 h72
  text "Plated" at 7059.52,965 h72
  text "Hole Type" at 7565.4,965 h72
  text "Hole Tolerance" at 8299.2,965 h72
  text "156" at 5370,815 h60
  text "12.00mil (0.305mm)" at 5959.84,815 h60
  text "PTH" at 7059.52,815 h60
  text "Round" at 7565.4,815 h60
  text "A" at 4835.03,805.01 h66.67
  text "2" at 5370,665 h60
  text "25.00mil (0.635mm)" at 5959.84,665 h60
  text "PTH" at 7059.52,665 h60
  text "Round" at 7565.4,665 h60
  text "B" at 4835.03,655.01 h66.67
  text "2" at 5370,515 h60
  text "32.00mil (0.813mm)" at 5959.84,515 h60
  text "PTH" at 7059.52,515 h60
  text "Round" at 7565.4,515 h60
  text "C" at 4835.03,505.01 h66.67
  text "14" at 5370,365 h60
  text "35.43mil (0.900mm)" at 5959.84,365 h60
  text "PTH" at 7059.52,365 h60
  text "Round" at 7565.4,365 h60
  text "D" at 4835.03,355.01 h66.67
  text "2" at 5370,215 h60
  text "39.37mil (1.000mm)" at 5959.84,215 h60
  text "PTH" at 7059.52,215 h60
  text "Round" at 7565.4,215 h60
  text "E" at 4835.03,205.01 h66.67
  text "176 Total" at 5370,65 h60

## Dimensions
0,1130 to 4525,1195 on Mechanical 13
-50,1080 to -110,0 on Mechanical 13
